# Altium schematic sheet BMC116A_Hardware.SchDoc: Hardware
size 431 x 279 mm; Date: Not shown in title block; ApprovedBy: Not shown in title block; CheckedBy: Not shown in title block; Author: Not shown in title block; CompanyName: Not shown in title block; Engineer: Not shown in title block; Organization: Not shown in title block; Address1: Not shown in title block; Address2: Not shown in title block; Address3: Not shown in title block; Address4: Not shown in title block; DocumentNumber: 3; Revision: Use project parameter SCH_Rev; SheetNumber: 2; SheetTotal: 2; PageSetup: Record=PageOptions¦CenterHorizontal=True¦CenterVertical=True¦PrintScale=1.00¦XCorrection=1.00¦YCorrection=1.00¦PrintKind=0¦BorderSize=5000000¦LeftOffset=0¦BottomOffset=0¦Orientation=2¦PaperLength=1000¦PaperWidth=1000¦Scale=100¦PaperSource=15¦PrintQuality=600¦MediaType=1¦DitherType=10¦PaperKind=Letter¦PrintScaleMode=1
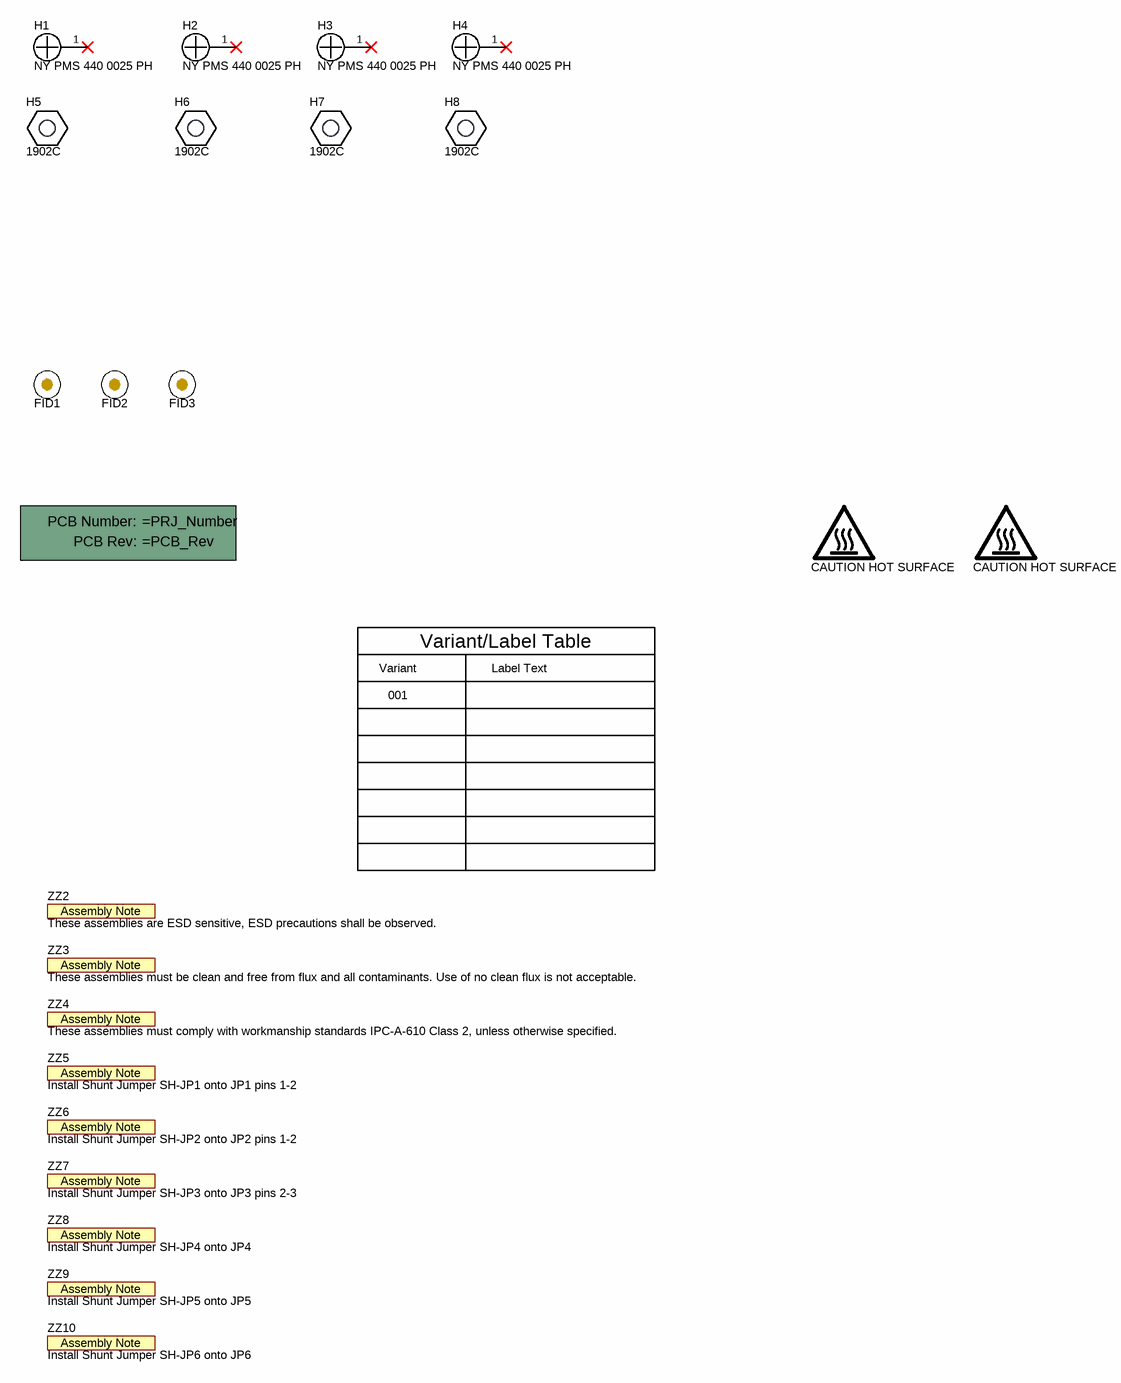
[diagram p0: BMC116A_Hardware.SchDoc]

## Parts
!PCB  Printed Circuit Board  (value not drawn)  (mechanical)
FID1  Fiducial  [Fiducial10-20]  (value not drawn)
FID2  Fiducial  [Fiducial10-20]  (value not drawn)
FID3  Fiducial  [Fiducial10-20]  (value not drawn)
H1  NY PMS 440 0025 PH  [NY PMS 440 0025 PH]
H2  NY PMS 440 0025 PH  [NY PMS 440 0025 PH]
H3  NY PMS 440 0025 PH  [NY PMS 440 0025 PH]
H4  NY PMS 440 0025 PH  [NY PMS 440 0025 PH]
H5  1902C  [Keystone_1902C]
H6  1902C  [Keystone_1902C]
H7  1902C  [Keystone_1902C]
H8  1902C  [Keystone_1902C]
Logo5  CAUTION HOT SURFACE  [IEC_HotSurface_Small]  (no BOM)
Logo6  CAUTION HOT SURFACE  [IEC_HotSurface_Small]  (no BOM)
ZZ2  These assemblies are ESD sensitive, ESD precautions shall be observed.  [AssemblyNote]  (no BOM)
ZZ3  These assemblies must be clean and free from flux and all contaminants. Use of no clean flux is not acceptable.  [AssemblyNote]  (no BOM)
ZZ4  These assemblies must comply with workmanship standards IPC-A-610 Class 2, unless otherwise specified.  [AssemblyNote]  (no BOM)
ZZ5  Install Shunt Jumper SH-JP1 onto JP1 pins 1-2  [AssemblyNote]  (no BOM)
ZZ6  Install Shunt Jumper SH-JP2 onto JP2 pins 1-2  [AssemblyNote]  (no BOM)
ZZ7  Install Shunt Jumper SH-JP3 onto JP3 pins 2-3  [AssemblyNote]  (no BOM)
ZZ8  Install Shunt Jumper SH-JP4 onto JP4  [AssemblyNote]  (no BOM)
ZZ9  Install Shunt Jumper SH-JP5 onto JP5  [AssemblyNote]  (no BOM)
ZZ10  Install Shunt Jumper SH-JP6 onto JP6  [AssemblyNote]  (no BOM)

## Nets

Not connected (* = marked no-connect by the designer): H1 1*; H2 1*; H3 1*; H4 1*

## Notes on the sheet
- Variant
- Variant/Label Table
- Label Text
- 001

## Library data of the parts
!PCB = CMP-0003618-2: Manufacturer: Any
FID1-FID3 = CMP-0077181-1: Fiducial mark.  There is nothing to buy or mount.
H1-H4 = CMP-0003617-1: Machine Screw, Round, #4-40 x 1/4, Nylon, Philips panhead; Manufacturer: B&F Fastener Supply; CompType: Hardware
H5-H8 = CMP-0003610-1: Standoff, Hex, 0.5"L #4-40 Nylon; Manufacturer: Keystone; CompType: Hardware
Logo5 Logo6 = CMP-0074837-2: IEC 61010-1 Hot Surface Warning; Manufacturer: Texas Instruments; CompType: IC; AEC Category: Q200; SymbolCreator: a0412235
ZZ2 = CMP-0077236-1
ZZ3 = CMP-0077237-1
ZZ4 = CMP-0077238-1
ZZ5-ZZ10 = CMP-0077238-1: These assemblies must comply with workmanship standards IPC-A-610 Class 2, unless otherwise specified.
